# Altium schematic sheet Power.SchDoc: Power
size A3; Author: J. Garnier; DrawnBy: J. Garnier; SheetNumber: 6; SheetTotal: 8
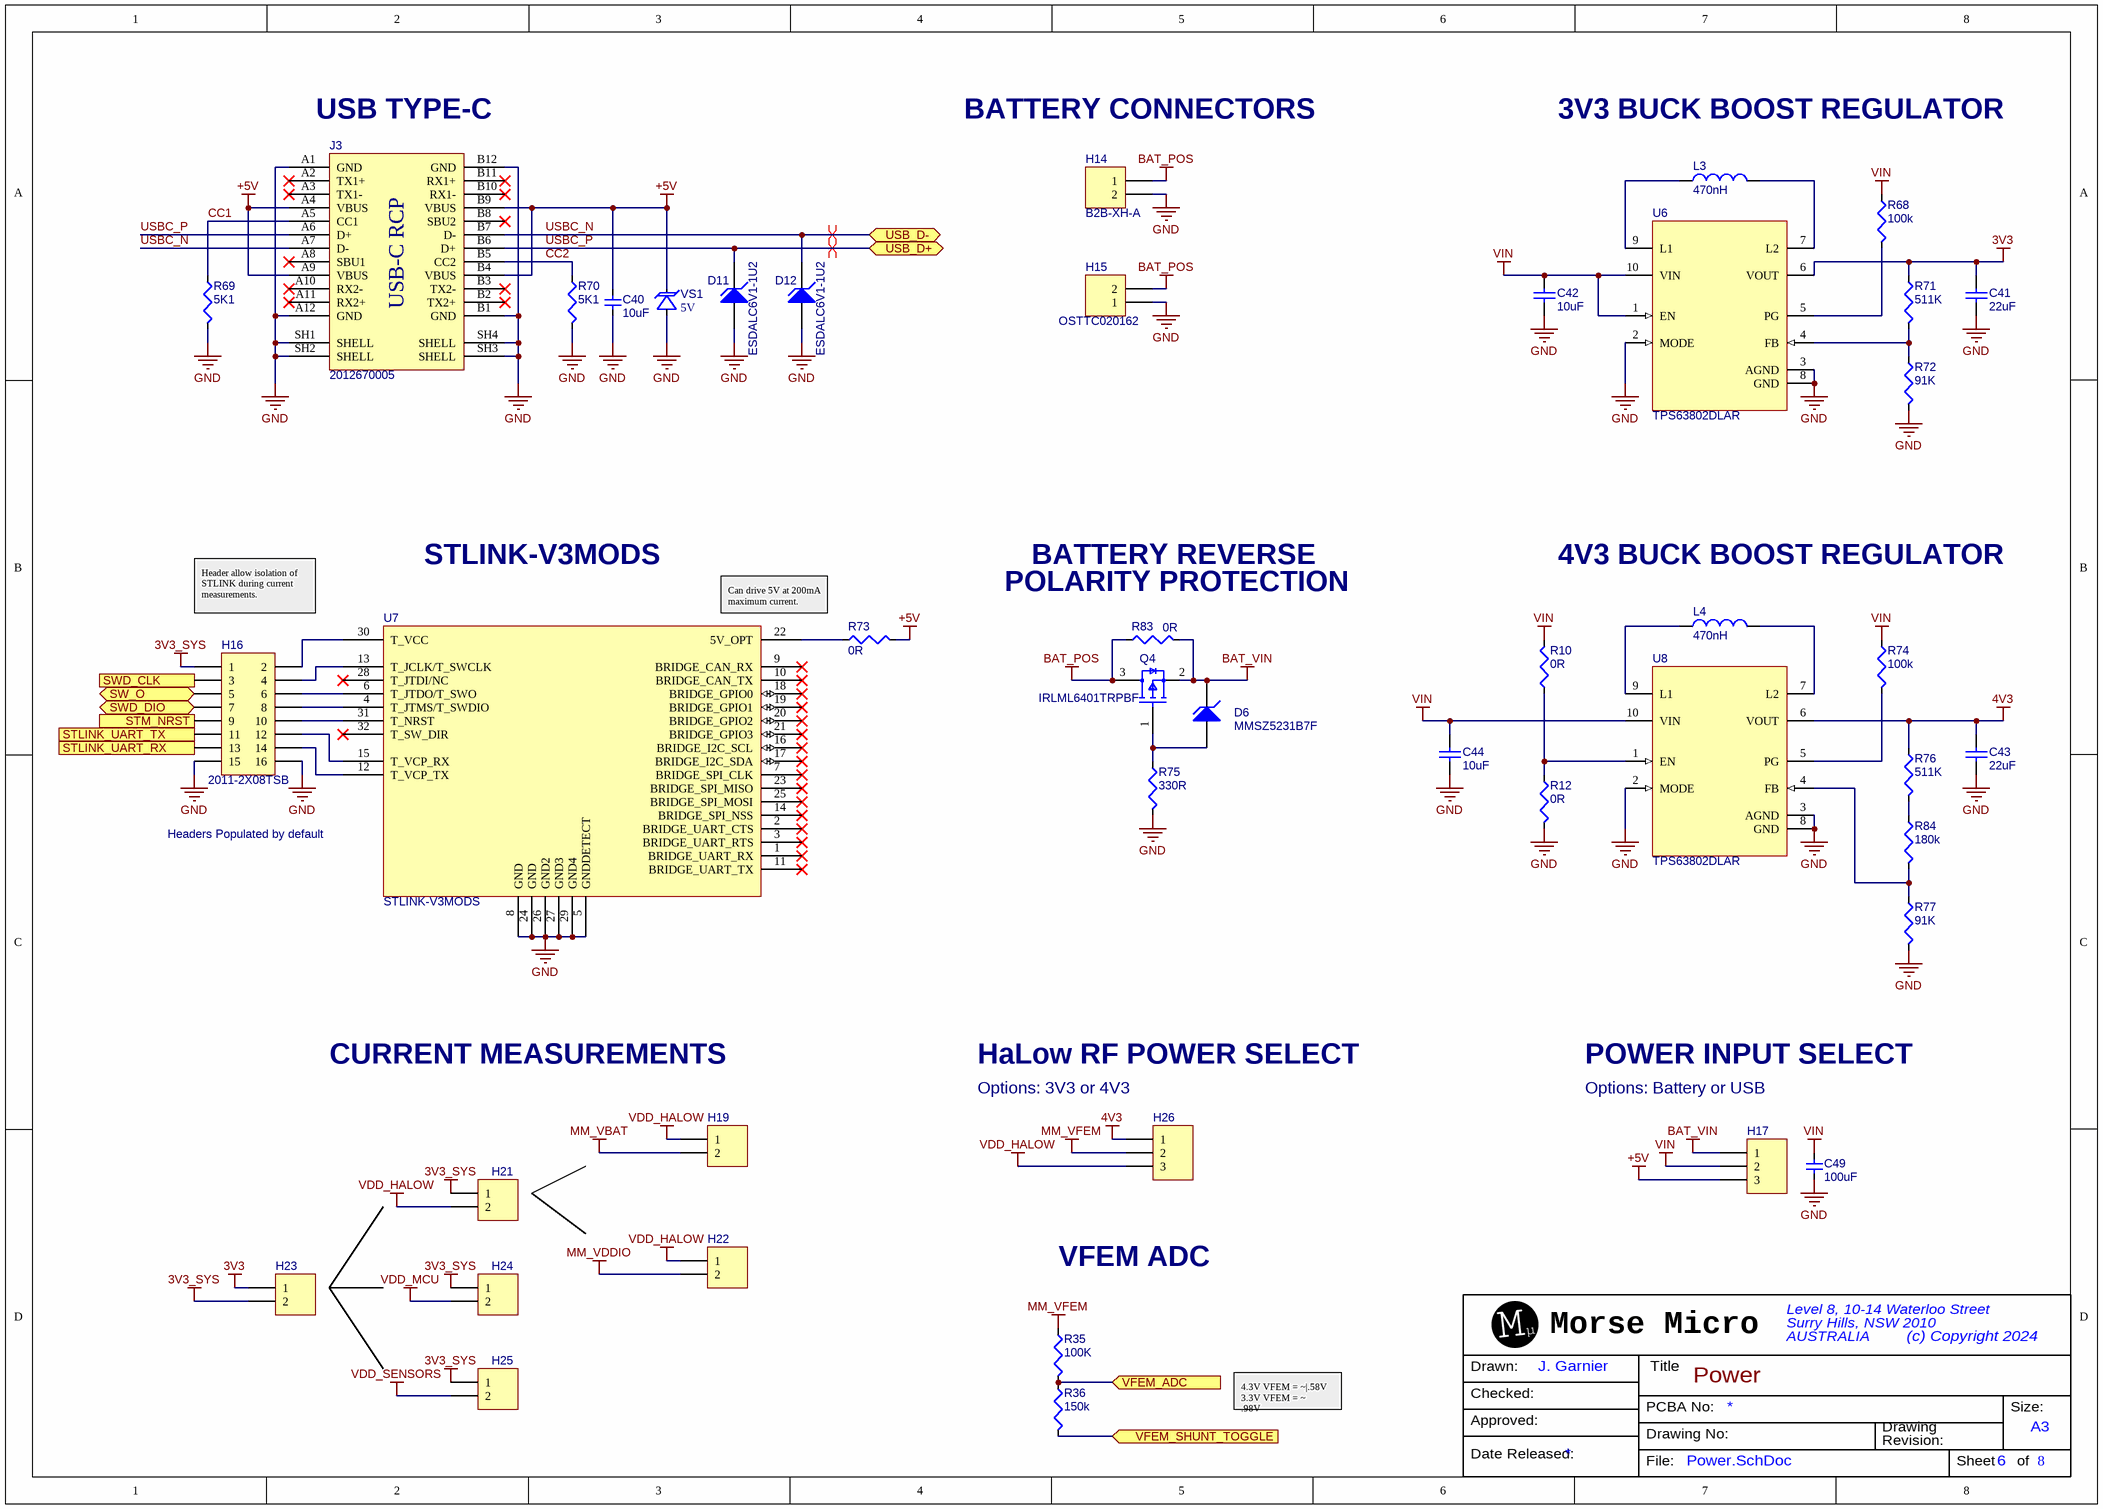
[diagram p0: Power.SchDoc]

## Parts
C40  value 10uF  [CAPC1608X06N]  (hidden comment: GRM188R61E106MA73J)
C41  value 22uF  [0603_cap]  (hidden comment: GRM188R60J226MEA0D)
C42  value 10uF  [0603_cap]  (hidden comment: GRM188R60J106ME84D)
C43  value 22uF  [0603_cap]  (hidden comment: GRM188R60J226MEA0D)
C44  value 10uF  [0603_cap]  (hidden comment: GRM188R60J106ME84D)
C49  value 100uF  [CAPC3225X20N]  (hidden comment: CL32A107MPVNNNE)
D6  MMSZ5231B7F  [SOD-123FL]
D11  ESDALC6V1-1U2  [0201_DIODE]
D12  ESDALC6V1-1U2  [0201_DIODE]
H14  B2B-XH-A  [B2B-XH-A]
H15  OSTTC020162  [SCREW_TERM_2WAY_5MM]
H16  2011-2X08TSB  [HDR2X8 Short Gold]
H17  2011-1X03G00SB  [HDR1X3]  (value not drawn)
H19  2011-1X02G00SB-1  [HDR1X2]  (value not drawn)
H21  2011-1X02G00SB-1  [HDR1X2]  (value not drawn)
H22  2011-1X02G00SB-1  [HDR1X2]  (value not drawn)
H23  2011-1X02G00SB-1  [HDR1X2]  (value not drawn)
H24  2011-1X02G00SB-1  [HDR1X2]  (value not drawn)
H25  2011-1X02G00SB-1  [HDR1X2]  (value not drawn)
H26  2011-1X03G00SB  [HDR1X3]  (value not drawn)
J3  2012670005  [USB-C_RCP]
L3  value 470nH  [INDC2520X120N]  (hidden comment: DFE252012PR47MP2)
L4  value 470nH  [INDC2520X120N]  (hidden comment: DFE252012PR47MP2)
Q4  IRLML6401TRPBF  [FP-SOT23-IPC_A]
R10  value 0R  [RESC1608X06N]  (hidden comment: RC0603JR-070RL)
R12  value 0R  [RESC1608X06N]  (hidden comment: RC0603JR-070RL)
R35  value 100K  [0402_res]  (hidden comment: RC0402FR-07100KL)
R36  value 150k  [0402_res]  (hidden comment: ERJ-2RKF1503X)
R68  value 100k  [RESC1005X04N]  (hidden comment: RC0402FR-07100KL)
R69  value 5K1  [RESC1005X04N]  (hidden comment: MCR01MZPF5101)
R70  value 5K1  [RESC1005X04N]  (hidden comment: MCR01MZPF5101)
R71  value 511K  [0402_res]  (hidden comment: RES0262)
R72  value 91K  [0402_res]  (hidden comment: RES0263)
R73  value 0R  [RESC1608X06N]  (hidden comment: RC0603JR-070RL)
R74  value 100k  [RESC1005X04N]  (hidden comment: RC0402FR-07100KL)
R75  value 330R  [RESC1005X04N]  (hidden comment: RC0402FR-07330RL)
R76  value 511K  [0402_res]  (hidden comment: RES0262)
R77  value 91K  [0402_res]  (hidden comment: RES0263)
R83  value 0R  [RESC1608X06N]  (hidden comment: RC0603JR-070RL)
R84  value 180k  [0402_res]  (hidden comment: MCR01MZPF1803)
U6  TPS63802DLAR  [TPS63802DLAR]
U7  STLINK-V3MODS  [STLINK-V3MODS]
U8  TPS63802DLAR  [TPS63802DLAR]
VS1  value 5V  [SOD-523]  (hidden comment: ESD5Z5.0T1G)

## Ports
STLINK_UART_RX (in, see Main[2B]), STLINK_UART_TX (out, see Main[2B]), STM_NRST (out, see Main[2B], STM_MCU[1B]), SW_O (bidir, see Main[2B], STM_MCU[4C]), SWD_CLK (out, see Main[2B], STM_MCU[5B]), SWD_DIO (bidir, see Main[2B], STM_MCU[5B]), USB_D+ (bidir, see Main[2B], STM_MCU[5B]), USB_D- (bidir, see Main[2B], STM_MCU[5B]), VFEM_ADC (in, see Main[2B], STM_MCU[5C]), VFEM_SHUNT_TOGGLE (in, see Main[2C], STM_MCU[8B])

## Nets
3V3: C41.2 H23.1 R71.1 U6.6(VOUT)
3V3_SYS: H16.1 H21.1 H23.2 H24.1 H25.1
4V3: C43.2 H26.1 R76.1 U8.6(VOUT)
+5V: C40.1 H17.3 J3.A4(VBUS) J3.A9(VBUS) J3.B4(VBUS) J3.B9(VBUS) R73.2 VS1.K
BAT_POS: H14.1 H15.2 Q4.3(D) R83.1
BAT_VIN: D6.K H17.1 Q4.2(S) R83.2
GND: C40.2 C41.1 C42.1 C43.1 C44.1 C49.2 D11.A D12.A H14.2 H15.1 H16.15 H16.16 J3.A1(GND) J3.A12(GND) J3.B1(GND) J3.B12(GND) J3.SH1(SHELL) J3.SH2(SHELL) J3.SH3(SHELL) J3.SH4(SHELL) R12.2 R69.2 R70.2 R72.2 R75.2 R77.2 U6.2(MODE) U6.3(AGND) U6.8(GND) U7.5(GNDDETECT) U7.8(GND) U7.24(GND) U7.26(GND2) U7.27(GND3) U7.29(GND4) U8.2(MODE) U8.3(AGND) U8.8(GND) VS1.A
MM_VBAT: H19.2
MM_VDDIO: H22.2
MM_VFEM: H26.2 R35.1
VDD_HALOW: H19.1 H21.2 H22.1 H26.3
VDD_MCU: H24.2
VDD_SENSORS: H25.2
VIN: C42.2 C44.2 C49.1 H17.2 R10.2 R68.1 R74.1 U6.1(EN) U6.10(VIN) U8.10(VIN)
CC1: J3.A5(CC1) R69.1
CC2: J3.B5(CC2) R70.1
STLINK_UART_RX: H16.13 ; port STLINK_UART_RX
STLINK_UART_TX: H16.11 ; port STLINK_UART_TX
STM_NRST: H16.9 ; port STM_NRST
SW_O: H16.5 ; port SW_O
SWD_CLK: H16.3 ; port SWD_CLK
SWD_DIO: H16.7 ; port SWD_DIO
USBC_N: D12.K J3.A7(D-) J3.B7(D-) ; port USB_D-
USBC_P: D11.K J3.A6(D+) J3.B6(D+) ; port USB_D+
VFEM_ADC: R35.2 R36.1 ; port VFEM_ADC
VFEM_SHUNT_TOGGLE: R36.2 ; port VFEM_SHUNT_TOGGLE
NetD6_A: D6.A Q4.1(G) R75.1
NetH16_2: H16.2 U7.30(T_VCC)
NetH16_4: H16.4 U7.13(T_JCLK/T_SWCLK)
NetH16_6: H16.6 U7.6(T_JTDO/T_SWO)
NetH16_8: H16.8 U7.4(T_JTMS/T_SWDIO)
NetH16_10: H16.10 U7.31(T_NRST)
NetH16_12: H16.12 U7.15(T_VCP_RX)
NetH16_14: H16.14 U7.12(T_VCP_TX)
NetL3_1: L3.1 U6.9(L1)
NetL3_2: L3.2 U6.7(L2)
NetL4_1: L4.1 U8.9(L1)
NetL4_2: L4.2 U8.7(L2)
NetR10_1: R10.1 R12.1 U8.1(EN)
NetR68_2: R68.2 U6.5(PG)
NetR71_2: R71.2 R72.1 U6.4(FB)
NetR73_1: R73.1 U7.22(5V_OPT)
NetR74_2: R74.2 U8.5(PG)
NetR76_2: R76.2 R84.1
NetR77_1: R77.1 R84.2 U8.4(FB)

Not connected (* = marked no-connect by the designer): J3 A2(TX1+)* A3(TX1-)* A8(SBU1)* A10(RX2-)* A11(RX2+)* B2(TX2+)* B3(TX2-)* B8(SBU2)* B10(RX1-)* B11(RX1+)*; U7 1(BRIDGE_UART_RX)* 2(BRIDGE_UART_CTS)* 3(BRIDGE_UART_RTS)* 7(BRIDGE_SPI_CLK)* 9(BRIDGE_CAN_RX)* 10(BRIDGE_CAN_TX)* 11(BRIDGE_UART_TX)* 14(BRIDGE_SPI_NSS)* 16(BRIDGE_I2C_SCL)* 17(BRIDGE_I2C_SDA)* 18(BRIDGE_GPIO0)* 19(BRIDGE_GPIO1)* 20(BRIDGE_GPIO2)* 21(BRIDGE_GPIO3)* 23(BRIDGE_SPI_MISO)* 25(BRIDGE_SPI_MOSI)* 28(T_JTDI/NC)* 32(T_SW_DIR)*

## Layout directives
differential pair: USBC_N, USBC_P

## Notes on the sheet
- (near J3) USB TYPE-C
- BATTERY CONNECTORS
- 3V3 BUCK BOOST REGULATOR
- STLINK-V3MODS
- BATTERY REVERSE
- 4V3 BUCK BOOST REGULATOR
- Header allow isolation of STLINK during current measurements.
- Can drive 5V at 200mA maximum current.
- (near R83) POLARITY PROTECTION
- Headers Populated by default
- CURRENT MEASUREMENTS
- HaLow RF POWER SELECT
- (near H26) Options: 3V3 or 4V3
- POWER INPUT SELECT
- Options: Battery or USB
- VFEM ADC
- 4.3V VFEM = ~|.58V
  3.3V VFEM = ~
  .98V

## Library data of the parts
C40 = CAP0197-5: CAP CER 10UF 25V ±20% X5R 0603; Generic Allowed: Yes; Subtype: Ceramic
C41 C43 = CAP0243-1: Multilayer Ceramic Capacitor, 22 uF, 6.3 V, ± 20%, X5R, 0603 [1608 Metric]; Voltage Rating (DC): 6.3V
C42 C44 = CAP0244-1: Multilayer Ceramic Capacitor, 10 uF, 6.3 V, ± 20%, X5R, 0603 [1608 Metric]; Voltage Rating: 6.3V
C49 = CAP0047-3: CAP CER 100UF 10V ±20% X5R 1210; Generic Allowed: Yes; Subtype: Ceramic
D6 = DIO0072-1: DIODE ZENER 5.1V 500MW SOD-123
D11 D12 = DIO0043-4: TVS DIODE 3VWM ST020; Power: 20W; Generic Allowed: No; Voltage: 3V
H14 = HDR0117-1: Board Connector, 2 Contact(s), 1 Row(s), Male, Straight, Solder Terminal,
H15 = JCK0020-1: CONN TERM BLOCK 5MM 2POS; Generic Allowed: Yes
H16 = HDR0116-2
H17 H26 = HDR0008-2: Conn Straight Header 3x1 0.100" 3 POS; Generic Allowed: Yes
H19 H21-H25 = HDR0006-2: Conn Straight Header 2x1 0.100" 2 POS; Generic Allowed: Yes
J3 = JCK0027-1: CONN RCP USB3.1 TYPEC 24P SMD RA; Generic Allowed: Yes
L3 L4 = IND0139-3: Generic Allowed: NO; Current: 4; DC Resistance: 27mOhm
Q4 = TSR0020-1: Small Signal Field-Effect Transistor; Transistor Element Material: SILICON; Drain-source On Resistance-Max: 50mR; Power Dissipation-Max (Abs): 1.3W; Drain Current-Max (Abs) (ID): 4.3A; Polarity/Channel Type: P-CHANNEL; Number of Elements: 1; DS Breakdown Voltage-Min: 12V; Transistor Application: SWITCHING; FET Technology: METAL-OXIDE SEMICONDUCTOR; Qualification Status: Not Qualified; Additional Feature: HIGH RELIABILITY; Operating Mode: ENHANCEMENT MODE; Avalanche Energy Rating (Eas): 33mJ; Pulsed Drain Current-Max (IDM): 34A; Package Body Material: Plastic; Time @ Peak Reflow Temperature-Max (s): 30s
R10 R12 R73 R83 = RES0119-6: RES SMD 0R OHM ±5% 1/10W 0603; Generic Allowed: Yes
R35 = RES0023-9: RES SMD 100K OHM ±1% 1/16W 0402; Generic Allowed: Yes
R36 = RES0252-6: RES SMD 150K OHM 1% 1/10W 0402; Subtype: Thick Film; Generic Allowed: Yes
R68 R74 = RES0044-8: RES SMD 100K OHM ±1% 1/16W 0402; Generic Allowed: Yes
R69 R70 = RES0094-8: RES SMD 5K1 OHM ±1% 1/16W 0402; Generic Allowed: Yes
R71 R76 = RES0254-2: RES 511K OHM 1% 1/16W 0402; Manufacturer 1: YAGEO; Manufacturer Part Number 1: RC0402FR-07511KL; Subtype: Thick Film; Generic Allowed: Yes
R72 R77 = RES0255-2: RES 91K OHM 1% 1/16W 0402; Manufacturer Part Number 1: RC0402FR-0791KL; Manufacturer 1: YAGEO; Generic Allowed: Yes; Subtype: Thick Film
R75 = RES0025-8: RES SMD 330R OHM ±1% 1/16W 0402; Generic Allowed: Yes
R84 = RES0057-9: RES SMD 180K OHM ±1% 1/16W 0402; Generic Allowed: Yes
U6 U8 = ICT0222-5: Generic Allowed: No
U7 = MOD0018-3
VS1 = DIO0073-1: TVS Diode,5V@9.4Amp, SOD-523 SMD; Current: 9.4A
